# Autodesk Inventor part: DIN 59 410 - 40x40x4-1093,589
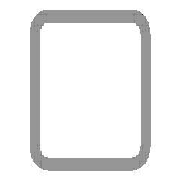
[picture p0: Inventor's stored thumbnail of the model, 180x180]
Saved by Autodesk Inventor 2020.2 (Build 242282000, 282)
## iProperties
Manager: www.cadconsulting.pl
Company: Fabian Stasiak CAD Consulting
IsCustomPart: 1
_CCFamilyMember: 20
_CCFamilyDisplayName: DIN 59410 (Kwadrat) - Rurki stalowe o przekroju kwadratowym formowane na gorąco
_FrameMemberDoc: Frame Member File
_Version: 15.0.0
_GetPNFromCC: 1
Created: 2015-01
Part Number: DIN 59 410 - 40x40x4-1093,589
Material: Stal, miękka
Description: Rurki stalowe o przekroju kwadratowym formowane na gorąco
Document SubType Name: Modellieren
Standard: DIN
Designer: F.Stasiak
Standards Organization: DIN
Language: pl-PL
Size Designation: 40x40x4
Categories: <MemberInstance><Categories><Category DisplayName="Kształtowniki konstrukcyjne" InternalName="089c4875-fa83-4c05-b084-43b9cc11f5ed" Mnemonic="GRDR"><CategoryPar
Stock Number: 40x40x4
Density: 7.85 g/cm^3
Appearance: Częściowo polerowana
Mass: 4393.44 g
Surface Area: 2813.5 cm^2
Volume: 559.674 cm^3
Catalog Web Link: www.expertbooks.pl
G_W: 40,000 mm
G_H: 40,000 mm
+E9637F4B-7AEF-41B5-AF55-0C21903EC1D5+CUTDETAIL1: Wytnij
+97E3A2D2-1B03-4D3D-9BA0-D5D38A2D39A1+CUTDETAIL2: Wytnij
G_L: 1093,589 mm
Author: F.Stasiak
Subject: Zbiór ćwiczeń. Autodesk Inventor 2020. Kurs Professional
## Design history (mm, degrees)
node "Płaszczyzna początkowa"
node "Płaszczyzna końcowa"
sketch "Szkic1"
  geometry: L1 (-12, 20)-(12, 20); L2 (20, 12)-(20, -12); L3 (12, -20)-(-12, -20); L4 (-20, -12)-(-20, 12); L5 (-30.32, 0)-(30.32, 0) reference; L6 (0, -30.32)-(0, 30.32) reference; L7 (-12, 16)-(12, 16); L8 (16, 12)-(16, -12); L9 (12, -16)-(-12, -16); L10 (-16, -12)-(-16, 12); A1 r 8 centre (-12, 12) between (-12, 20) and (-20, 12); A2 r 8 centre (12, 12) between (20, 12) and (12, 20); A3 r 8 centre (12, -12) between (12, -20) and (20, -12); A4 r 8 centre (-12, -12) between (-20, -12) and (-12, -20); A5 r 4 centre (-12, 12) between (-12, 16) and (-16, 12); A6 r 4 centre (12, 12) between (16, 12) and (12, 16); A7 r 4 centre (12, -12) between (12, -16) and (16, -12); A8 r 4 centre (-12, -12) between (-16, -12) and (-12, -16); 3 further points
  constraints: 16 end point, 16 point on circle, 8 centre point, 8 tangent, 6 point on line, 4 parallel, 3 equal radius, 3 perpendicular, 1 horizontal, 7 other
  dimensions: "b" = 40 distance of point (-20, 20) point (20, 20); "msp_r" = 8 radius of A1 (= 2 x ParT); "d8" = 20 distance between parallel lines of L4 L6 (= d9); "d9" = 20 distance between parallel lines of L3 L5 (= 0.5 x b); "d10" = 4 distance between parallel lines of L3 L9 (= ParT)
extrude "Bryła" new body sketch "Szkic1" taper "d4" = 0 deg; stored distance "NLG" = 10
node "Driven Length"
  sketch "Sketch2"
    geometry: L1 (0, 0)-(10, 0) reference
    constraints: 2 end point, 1 horizontal
  workplane "Work Plane3"
  sketch "Sketch3"
    geometry: L1 (-2, 15.355)-(12, 15.355) reference; L2 (-2, 1108.944)-(12, 1108.944) reference
    dimensions: "d14" = 1093.5891 distance between parallel lines of L1 L2 (derived)
node "Płaszczyzna konstrukcyjna4"
feature "Podział1"
node "Płaszczyzna konstrukcyjna5"
feature "Podział2"
body "Solid1"
other parameters: "ParT" = 4, "G_OFFSET_START" = -15.35534 [user parameter; used in 1 equation term], "G_OFFSET_END" = -22.42641 [user parameter; used in 1 equation term], "d11" = 15.35534 (= -G_OFFSET_START), "d12" = 1108.94444 (= G_OFFSET_END + B_L), "G_L" = 1093.5891 (= d14) [user parameter], "B_L" = 1131.37085 [user parameter; used in 1 equation term], "d13" = 90 deg
